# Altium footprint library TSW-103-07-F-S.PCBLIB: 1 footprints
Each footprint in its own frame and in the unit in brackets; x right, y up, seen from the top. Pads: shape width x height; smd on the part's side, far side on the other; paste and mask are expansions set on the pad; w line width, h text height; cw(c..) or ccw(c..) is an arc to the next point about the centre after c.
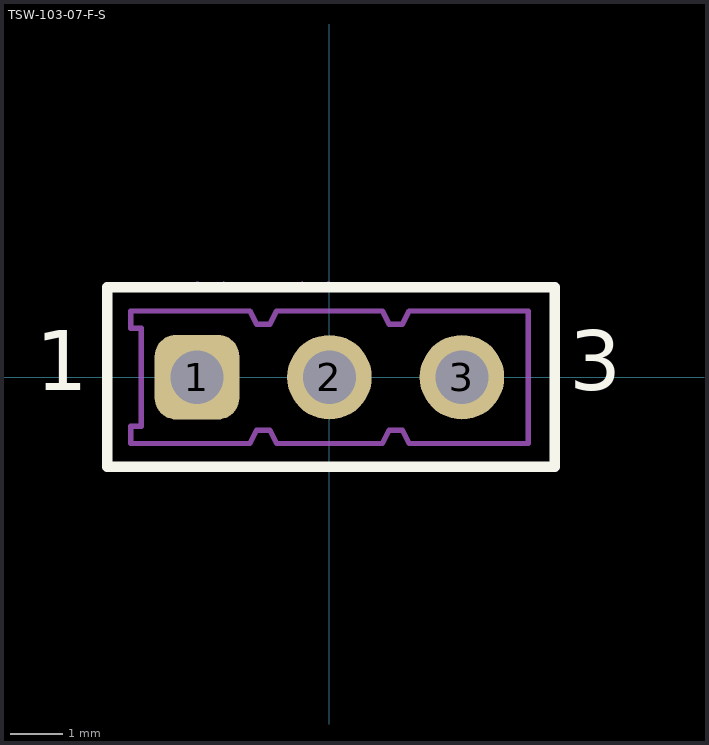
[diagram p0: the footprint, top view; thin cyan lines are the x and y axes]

## TSW-103-07-F-S [mm]
pads (3):
  rrect50% 1.62x1.62 hole 1.02: 1(-2.54,0)
  round 1.62 hole 1.02: 2(0,0) 3(2.54,0)
Top Overlay:
  lines w0.2: -4.26,-1.72 -4.26,1.72 4.318,1.72 4.318,-1.72 -4.26,-1.72
  text "1" at -5.63,-0.635 h1.97
  text "3" at 4.601,-0.635 h1.97
Top Solder:
  circle w0: c2.54,0 r0.861
  circle w0: c-2.54,0 r0.861
  circle w0: c0,0 r0.861
Bottom Solder:
  circle w0: c2.54,0 r0.861
  circle w0: c-2.54,0 r0.861
  circle w0: c0,0 r0.861
Mechanical 16:
  lines w0.1: -3.81,-1.27 -3.81,-0.94 -3.607,-0.94 -3.607,0.94 -3.81,0.94 -3.81,1.27 -1.524,1.27 -1.4,1.016 -1.27,1.016 -1.14,1.016 -1.016,1.27 1.016,1.27 1.14,1.016 1.27,1.016 1.4,1.016 1.524,1.27 3.81,1.27 3.81,-1.27 1.524,-1.27 1.4,-1.016 1.27,-1.016 1.14,-1.016 1.016,-1.27 -1.016,-1.27 -1.14,-1.016 -1.27,-1.016 -1.4,-1.016 -1.524,-1.27 -3.81,-1.27 ; -2.858,-0.318 -2.858,0.318 -2.222,0.318 -2.222,-0.318 -2.858,-0.318 ; -0.318,-0.318 -0.318,0.318 0.318,0.318 0.318,-0.318 -0.318,-0.318 ; 2.222,-0.318 2.222,0.318 2.858,0.318 2.858,-0.318 2.222,-0.318
  text "3" at 4.601,-0.635 h1.97
  text "1" at -5.63,-0.635 h1.97
Mechanical 40:
  lines w0: -2.54,1.842 -1.905,1.683 -2.032,1.842 ; -0.572,1.762 -0.635,1.683 ; -0.508,1.842 -0.635,1.683 ; 0,1.842 -0.635,1.683
Mechanical 42:
  lines w0.1: -4.26,-1.72 -4.26,1.72 4.318,1.72 4.318,-1.72 -4.26,-1.72
3D body "TSW-103-07-F-S.stp": height 8.38, standoff -2.54, extent -3.847,-1.267 3.9,1.273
